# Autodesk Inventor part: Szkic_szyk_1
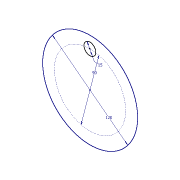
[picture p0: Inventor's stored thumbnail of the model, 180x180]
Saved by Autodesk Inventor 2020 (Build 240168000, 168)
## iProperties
Created: 2013-12
Part Number: Szkic_szyk_1
Material: Ogólny
Document SubType Name: Modeling
Designer: F.Stasiak
Density: 1 g/cm^3
Appearance: Domyślna
Manager: www.cadconsulting.pl
Company: Fabian Stasiak CAD Consulting
Author: F.Stasiak
Subject: Zbiór ćwiczeń. Autodesk Inventor 2020. Kurs podstawowy
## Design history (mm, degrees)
sketch "Szkic1" dims "d1" = 90
  geometry: C1 r 60 at (0, 0); C2 r 7.5 at (-0.342, 44.999); 2 further points
  constraints: 2 centre point, 1 coincident, 4 other
  dimensions: "d0" = 120 dimension on point (0, 0) C1.centre C1 point (0, 0) C2.centre C2; "d0" = 120 diameter of C1; "d2" = 15 diameter of C2
